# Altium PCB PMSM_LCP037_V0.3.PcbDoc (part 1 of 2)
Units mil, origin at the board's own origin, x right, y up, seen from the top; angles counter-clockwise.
Board outline 6102.36 x 5157.48 mil, 2 copper layers (Top Layer, Bottom Layer); 134 components, 72 nets, 340 pads, 815 vias.
Unrouted connection lines stored in the file: 2.
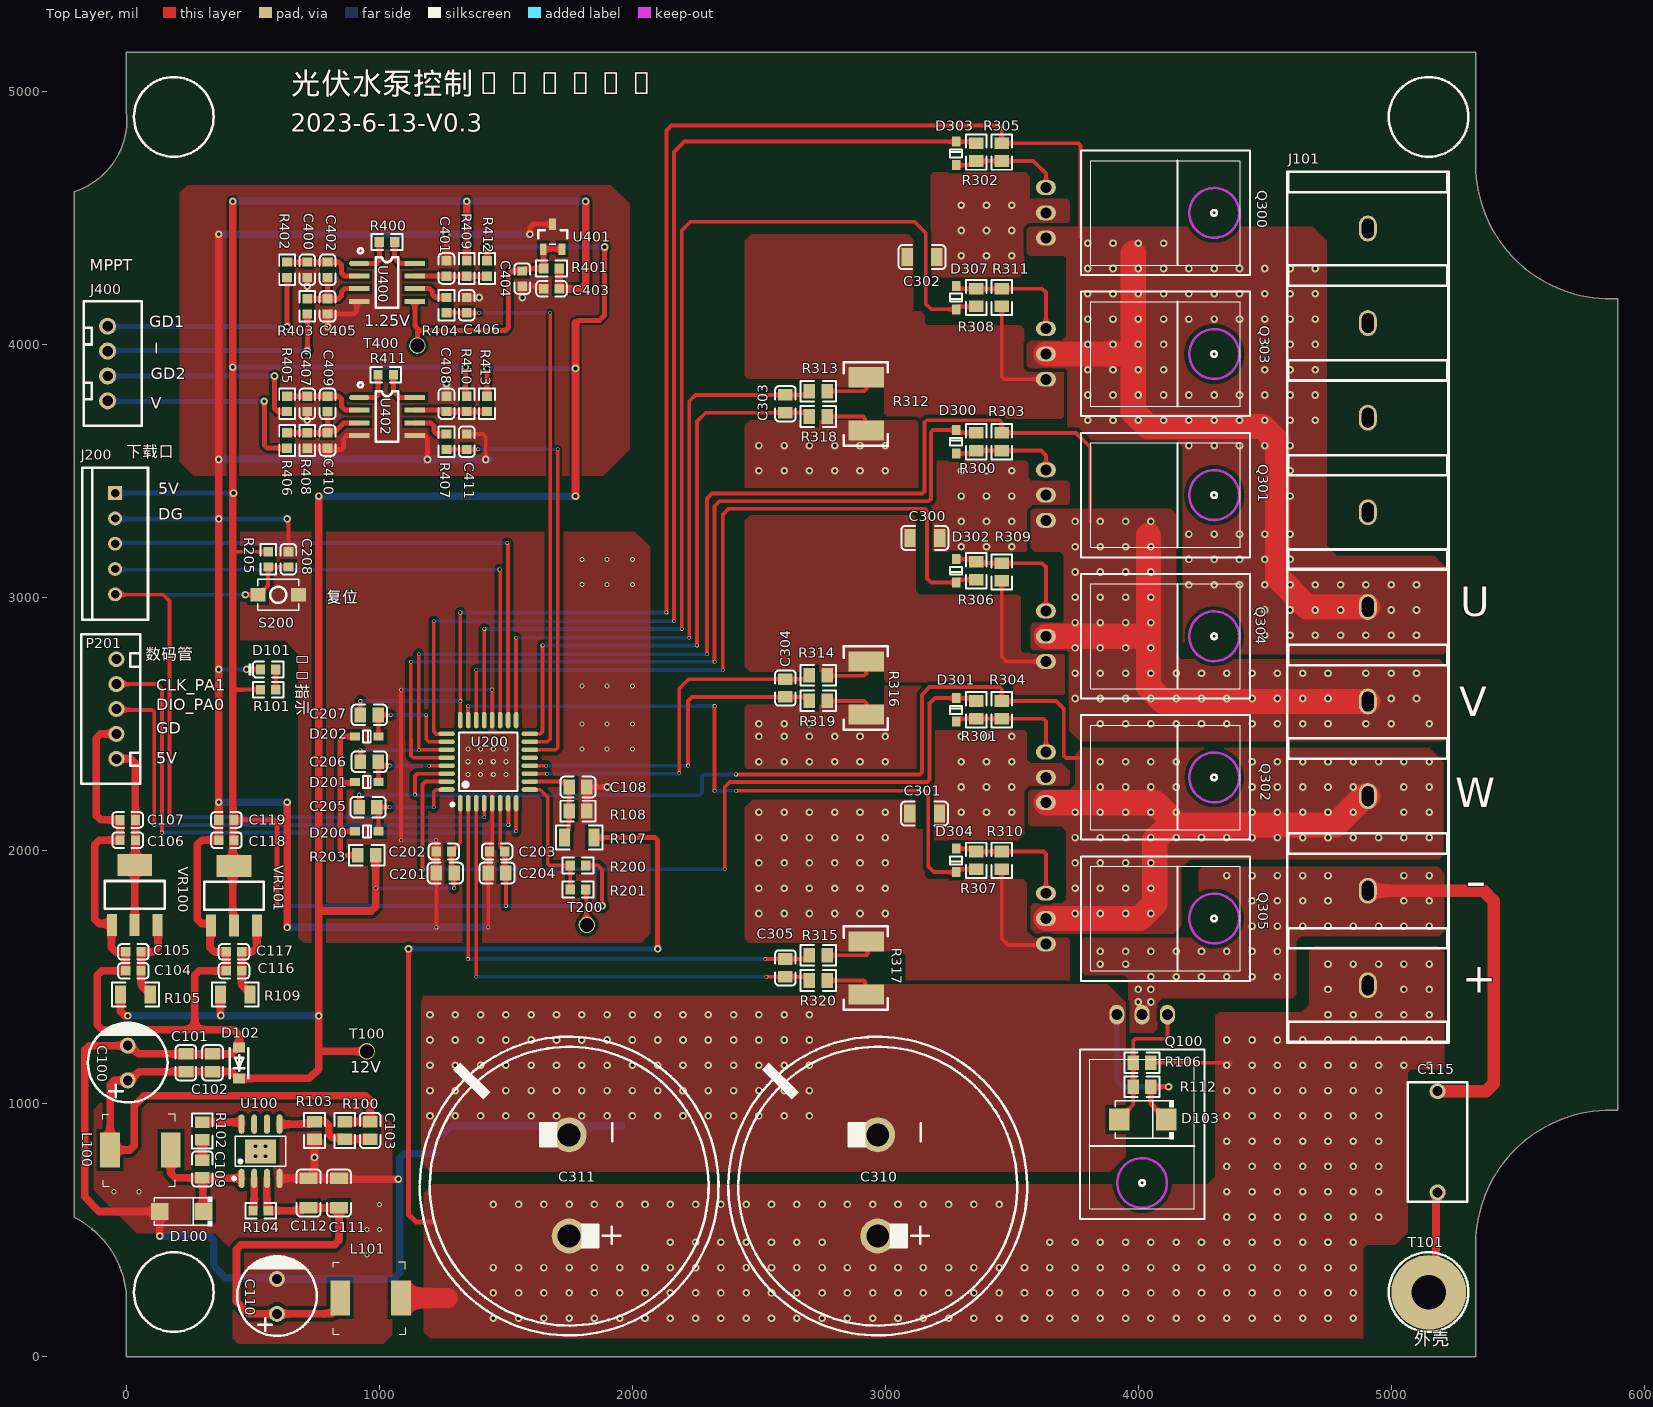
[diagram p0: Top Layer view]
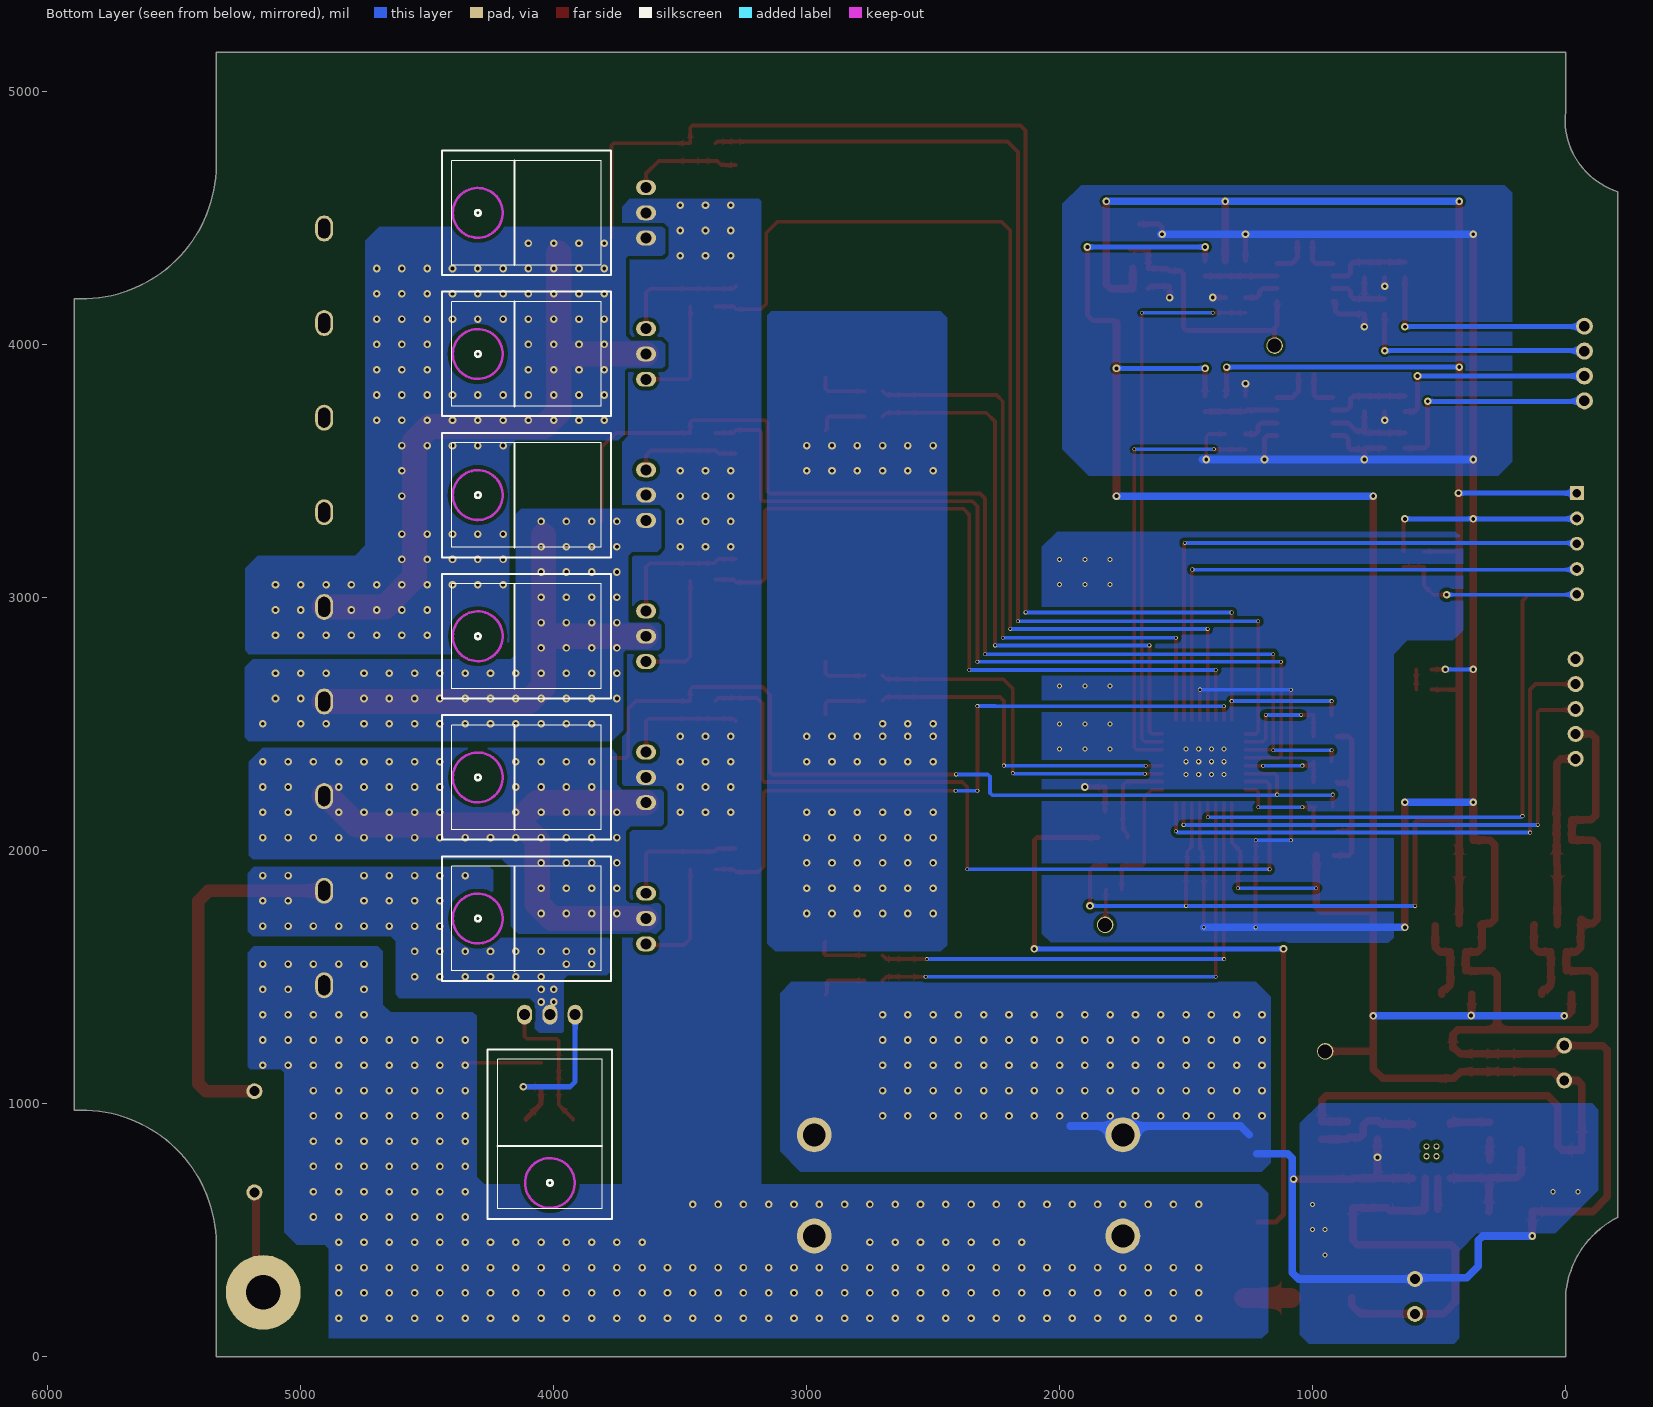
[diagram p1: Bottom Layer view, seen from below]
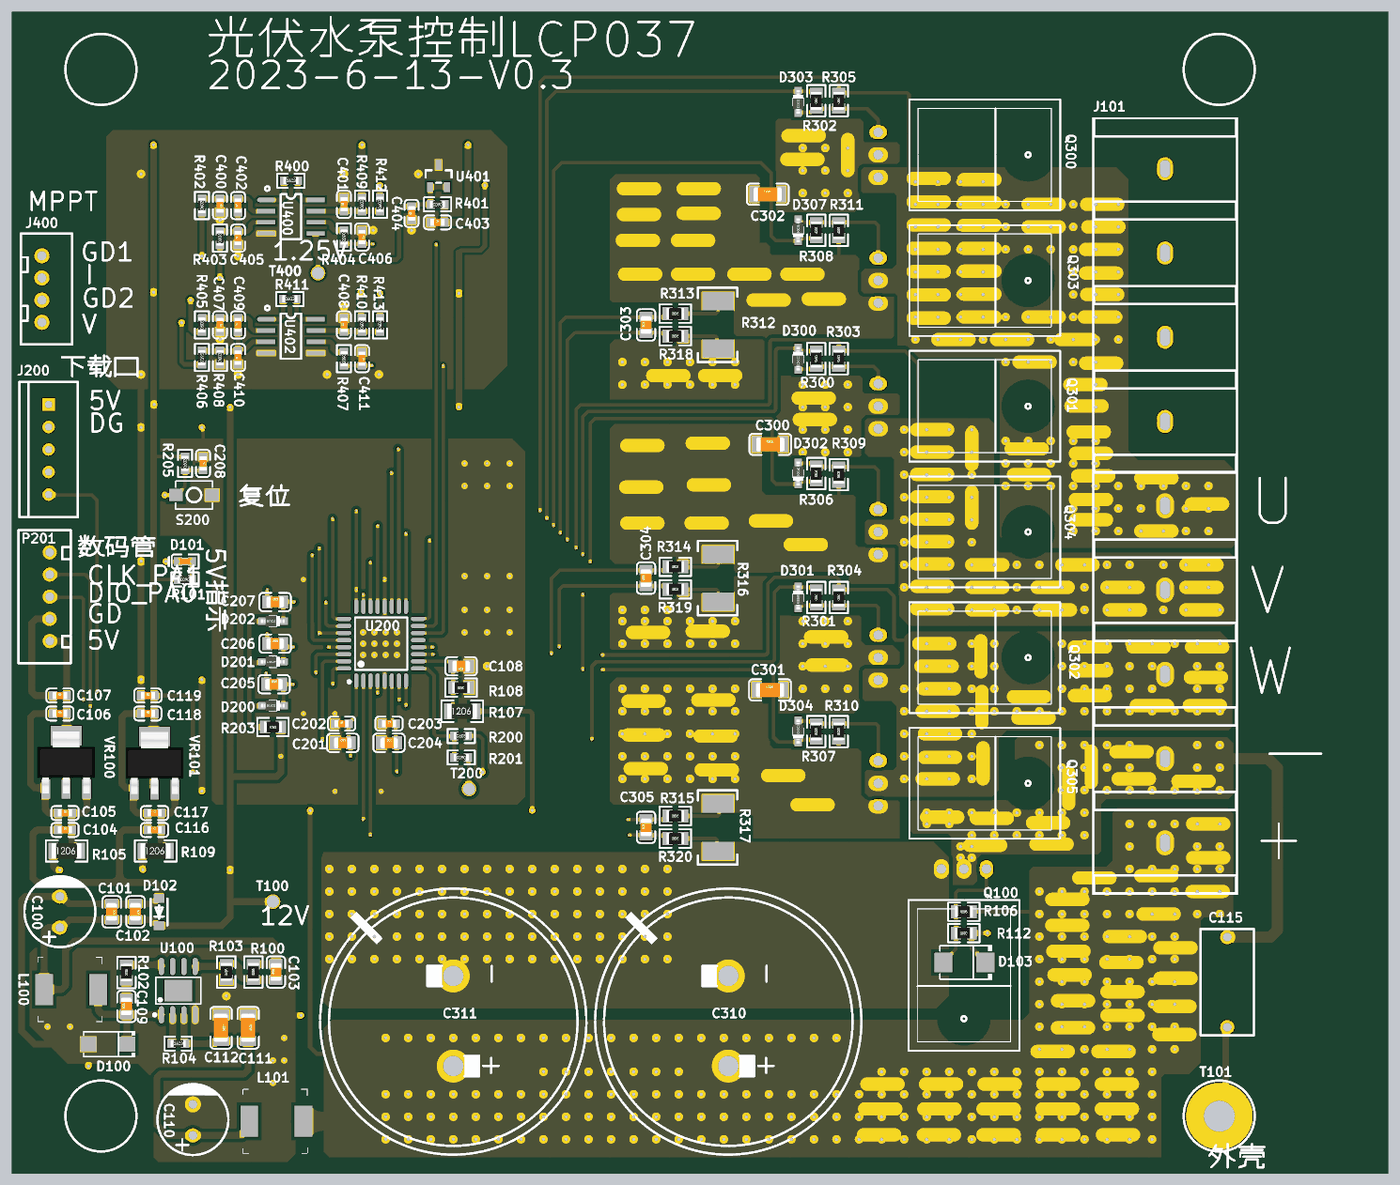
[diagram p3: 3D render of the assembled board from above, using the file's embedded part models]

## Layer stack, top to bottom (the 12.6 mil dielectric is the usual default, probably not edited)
Top Solder: solder mask 0.4, Solder Resist, Dk 3.5
Top Layer: signal copper 1.4
Dielectric 1: dielectric 12.6, FR-4, Dk 4.8
Bottom Layer: signal copper 1.4
Bottom Solder: solder mask 0.4, Solder Resist, Dk 3.5

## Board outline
0,-2.48 0,233.74 ccw(c-374.92,213) -206.69,548.7 -206.69,4603.82 ccw(c-297.17,4888.49) 0,4918.78 0,5155 5334.65,5155 5334.65,4682.56 ccw(c5866.14,4712.09) 5895.67,4180.59 5895.67,971.93 ccw(c5866.14,440.43) 5334.65,469.96 5334.65,-2.48

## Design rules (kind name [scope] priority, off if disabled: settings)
Clearance [All] p1: gap=10 ignorepadtopadclearanceinfootprint=FALSE
ComponentClearance [All] p1: gap=0 collisioncheckmode=3 verticalgap=0 showdistances=FALSE
HoleSize [All] p1: absolutevalues=TRUE maxlimit=500 minlimit=1 maxpercent=80.000 minpercent=20.000
HoleToHoleClearance [All] p1: gap=0 allowstackedmicrovias=TRUE
MinimumSolderMaskSliver [All] p1: minsoldermaskwidth=0
PlaneConnect [All] p1: planeconnectstyle=Direct reliefexpansion=20 reliefentries=4 reliefconductorwidth=10 reliefairgap=10
PolygonConnect [All] p1: connectstyle=Direct reliefconductorwidth=10 reliefentries=4 polygonreliefangle="90 Angle" airgapwidth=10
RoutingVias [All] p1: holewidth=10 width=15 viastyle="Through Hole" minholewidth=10 minwidth=15 maxholewidth=500 maxwidth=500
SilkToSilkClearance [All] p1: silktosilkclearance=0
SilkToSolderMaskClearance [IsPad] p1: minsilkscreentomaskgap=0 clearancetoexposedcopper=TRUE
SolderMaskExpansion [All] p1: expansion=4 istentingtop=FALSE
Width [All] p1: maxlimit=500 minlimit=6 preferedwidth=10
23 further rules are at their usual default settings.

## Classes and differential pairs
component class 04_AD623: C400 C401 C402 C403 C404 C405 C406 C407 C408 C409 C410 C411 J400 R400 R401 R402 R403 R404 R405 R406 R407 R408 R409 R410 R411 R412 R413 T400 U400 U401 U402
component class 03_Mos: C300 C301 C302 C303 C304 C305 C310 C311 D300 D301 D302 D303 D304 D307 Q300 Q301 Q302 Q303 Q304 Q305 R300 R301 R302 R303 R304 R305 R306 R307 R308 R309 R310 R311 R312 R313 R314 R315 R316 R317 R318 R319 R320
component class 02_MCU: C201 C202 C203 C204 C205 C206 C207 C208 D200 D201 D202 J200 P201 R200 R201 R203 R205 S200 T200 U200
component class 01_Power: C100 C101 C102 C103 C104 C105 C106 C107 C108 C109 C110 C111 C112 C115 C116 C117 C118 C119 D100 D101 D102 D103 J101 L100 L101 Q100 R100 R101 R102 R103 R104 R105 R106 R107 R108 R109 R112 T100 T101 U100 VR100 VR101

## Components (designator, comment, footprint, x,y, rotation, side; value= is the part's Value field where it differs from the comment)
C100 "470uF/25V" 47UF/100V 5,1090 r90 top
C101 "22uF (226) 20% 25V" 0805_C 235,1160 r270 top
C102 "100nF(104) 10% 50V" 0805_C 340,1160 r270 top
C103 "47pF (470) 5% 50V" 0805_C 963.31,892.52 r90 top
C104 "100nF (104) 10% 50V" 0603_C 27.48,1523.31 r0 top
C105 "10uF (106) 10% 10V" 0603_C 27.48,1598.31 r0 top
C106 "100nF (104) 10% 50V" 0603_C 5,2040 r0 top
C107 "10uF (106) 10% 10V" 0603_C 5,2120 r0 top
C108 "100nF(104) 10% 50V" 0805_C 1785,2250 r180 top
C109 "100nF(104) 10% 50V" 0805_C 300,740 r90 top
C110 "47uF/100V" 47UF/100V 595,167.2 r90 top
C111 "2.2uF (225) 10% 50V" 1206_C 840,645 r270 top
C112 "100nF (104) 10% 50V" 1206_C 720,645 r270 top
C115 "2.2nF (222) 10% 50V" "X1/Y1 500V" 5183.31,1047.52 r270 top
C116 "100nF (104) 10% 50V" 0603_C 425,1523.31 r0 top
C117 "10uF (106) 10% 10V" 0603_C 425,1598.31 r0 top
C118 "100nF (104) 10% 50V" 0603_C 395,2040 r0 top
C119 "10uF (106) 10% 10V" 0603_C 395,2120 r0 top
C201 "10uF (106) 10% 25V" 0805_C 1259.96,1910 r0 top
C202 "100nF (104) 10% 50V" 0603_C 1255,1995 r0 top
C203 "100nF (104) 10% 50V" 0603_C 1465,1995 r0 top
C204 "10uF (106) 10% 25V" 0805_C 1465,1910 r0 top
C205 "10uF (106) 10% 25V" 0805_C 955,2170 r0 top
C206 "10uF (106) 10% 25V" 0805_C 959.88,2350 r0 top
C207 "10uF (106) 10% 25V" 0805_C 959.88,2535 r0 top
C208 "100nF (104) 10% 50V" 0603_C 640,3150 r270 top
C300 "100nF (104) 10% 100V" 1206_C 3156.34,3235 r0 top
C301 "100nF (104) 10% 100V" 1206_C 3155,2145 r0 top
C302 "100nF (104) 10% 100V" 1206_C 3145,4345 r0 top
C303 "100pF (101) 5% 50V" 0805_C 2605,3765 r90 top
C304 "100pF (101) 5% 50V" 0805_C 2605,2641.22 r90 top
C305 "100pF (101) 5% 50V" 0805_C 2605,1535 r90 top
C310 "1000uF/250V" 1000UF/250V 2970,475 r90 top
C311 "1000uF/250V" 1000UF/250V 1750,475 r90 top
C400 "1nF (102) 10% 50V" 0603_C 715,4295 r270 top
C401 "100nF (104) 10% 50V" 0603_C 1265,4300 r90 top
C402 "47nF (473) 10% 50V" 0603_C 795,4295 r90 top
C403 "100nF (104) 10% 50V" 0603_C 1680.31,4220 r0 top
C404 "100nF (104) 10% 50V" 0603_C 1565,4260 r90 top
C405 "1nF (102) 10% 50V" 0603_C 795,4150 r90 top
C406 "100nF (104) 10% 50V" 0603_C 1345,4155 r270 top
C407 "1nF (102) 10% 50V" 0603_C 715,3765 r270 top
C408 "100nF (104) 10% 50V" 0603_C 1265,3765 r90 top
C409 "47nF (473) 10% 50V" 0603_C 795,3765 r90 top
C410 "1nF (102) 10% 50V" 0603_C 795,3620 r90 top
C411 "100nF (104) 10% 50V" 0603_C 1345,3615 r270 top
D100 "SS310" SS310 215,570 r180 top
D101 "绿灯 0603" 0603_LED_S1 560,2715 r0 top
D102 "SMF12A" "SMF12A - DUPLICATE" 445,1097.95 r90 top
D103 "SMBJ18A" SMBJ18A 4110,935 r180 top
D200 "1N4148WS T4" SOD-323 950,2075 r180 top
D201 "1N4148WS T4" SOD-323 949.88,2270 r180 top
D202 "1N4148WS T4" SOD-323 949.88,2450 r180 top
D300 "1N4148WS T4" SOD-323 3280,3615 r270 top
D301 "1N4148WS T4" SOD-323 3280,2555.04 r270 top
D302 "1N4148WS T4" SOD-323 3280,3105 r90 top
D303 "1N4148WS T4" SOD-323 3280,4755 r270 top
D304 "1N4148WS T4" SOD-323 3280,1960 r90 top
D307 "1N4148WS T4" SOD-323 3280,4185 r90 top
J101 "CON9" "CON9 9.5MM" 4907.48,1466.02 r90 top locked
J200 "SWD-KF2510-5P" 2.54_5P_PHI -45,3411.85 r270 top
J400 "CON4" XH2.54-4P -75,4071.85 r90 top
L100 "47uH/0650" 0650_47UH 45,815 r180 top
L101 "47uH/0650" 0650_47UH 955,230 r180 top
P201 "Header 5" XH2.54-5P -40,2755.28 r270 top
Q100 "NCEP1570" NCEP1570 4015,1507.48 r180 top locked
Q300 "NCEP1570" NCEP1570 3477.52,4520 r270 top locked
Q301 "NCEP1570" NCEP1570 3477.52,3404 r270 top
Q302 "NCEP1570" NCEP1570 3477.52,2288 r270 top
Q303 "NCEP1570" NCEP1570 3477.52,3962 r270 top
Q304 "NCEP1570" NCEP1570 3477.52,2846 r270 top
Q305 "NCEP1570" NCEP1570 3477.52,1730 r270 top
R100 "330KΩ (3303) ±1%" 0805_R 863.31,892.52 r90 top
R101 "10KΩ (1002) ±1%" 0603_R 560,2635 r180 top
R102 "22Ω (22R0) ±1%" 0805_R 300,890 r90 top
R103 "23.7KΩ" 0805_R 743.31,892.52 r90 top
R104 "30mΩ ±1%" 0603_R 530,575 r0 top
R105 "200Ω (2000) ±1%" 1206_R 35,1430 r0 top
R106 "20KΩ (2002) ±1%" 0805_R 4015,1160 r0 top
R107 "24KΩ (2402) ±1%" 1206_R 1790,2050 r0 top
R108 "1KΩ (1001) ±1%" 0805_R 1785,2155 r180 top
R109 "200Ω (2000) ±1%" 1206_R 430,1430 r0 top
R112 "10KΩ (1002) ±1%" 0805_R 4015,1065 r180 top
R200 "1KΩ (1001) ±1%" 0603_R 1785,1940 r0 top
R201 "1KΩ (1001) ±1%" 0603_R 1785,1845 r180 top
R203 "1KΩ (1001) ±1%" 0805_R 950,1980 r180 top
R205 "10KΩ (1002) ±1%" 0603_R 560,3150 r90 top
R300 "51Ω (51R0) ±1%" 0805_R 3360,3615 r270 top
R301 "51Ω (51R0) ±1%" 0805_R 3360,2555.04 r270 top
R302 "51Ω (51R0) ±1%" 0805_R 3360,4760 r270 top
R303 "100KΩ (1003) ±1%" 0805_R 3460,3615 r270 top
R304 "100KΩ (1003) ±1%" 0805_R 3460,2555.04 r270 top
R305 "100KΩ (1003) ±1%" 0805_R 3460,4760 r270 top
R306 "51Ω (51R0) ±1%" 0805_R 3360,3105 r90 top
R307 "51Ω (51R0) ±1%" 0805_R 3360,1960 r90 top
R308 "51Ω (51R0) ±1%" 0805_R 3360,4185 r90 top
R309 "100KΩ (1003) ±1%" 0805_R 3460,3100 r90 top
R310 "100KΩ (1003) ±1%" 0805_R 3460,1960 r90 top
R311 "100KΩ (1003) ±1%" 0805_R 3460,4185 r90 top
R312 "10mR 2512" R2512 2965,3790 r90 top
R313 "68Ω (68R0) ±1%" 0805_R 2735,3815 r0 top
R314 "68Ω (68R0) ±1%" 0805_R 2735,2691.22 r0 top
R315 "68Ω (68R0) ±1%" 0805_R 2735,1585 r0 top
R316 "10mR 2512" R2512 2965,2666.22 r90 top
R317 "10mR 2512" R2512 2965,1559.53 r90 top
R318 "68Ω (68R0) ±1%" 0805_R 2735,3715 r0 top
R319 "68Ω (68R0) ±1%" 0805_R 2735,2591.22 r0 top
R320 "68Ω (68R0) ±1%" 0805_R 2735,1485 r0 top
R400 "5.1KΩ (5101) ±1%" 0603_R 1030,4405 r0 top
R401 "220Ω (2200) ±1%" 0603_R 1680.32,4300 r180 top
R402 "1KΩ (1001) ±1%" 0603_R 635,4295 r90 top
R403 "1KΩ (1001) ±1%" 0603_R 715,4150 r90 top
R404 "100Ω (1000) ±1%" 0603_R 1265,4155 r270 top
R405 "1KΩ (1001) ±1%" 0603_R 635,3765 r90 top
R406 "20KΩ (2002) ±1%" 0603_R 635,3620 r270 top
R407 "100Ω (1000) ±1%" 0603_R 1265,3615 r270 top
R408 "1KΩ (1001) ±1%" 0603_R 715,3620 r90 top
R409 "0Ω (0R0) ±1%" 0603_R 1345,4300 r90 top
R410 "0Ω (0R0) ±1%" 0603_R 1345,3765 r90 top
R411 "0Ω (0R0) ±1%" 0603_R 1025,3880 r0 top
R412 "0Ω (0R0) ±1%" 0603_R 1425,4300 r90 top
R413 "0Ω (0R0) ±1%" 0603_R 1425,3765 r90 top
S200 "KEY" 按键3*4 519.76,3010 r0 top
T100 "Test" TESTPOINT 950,1205 r90 top
T101 "Test" 接地螺丝孔 5148.31,252.52 r0 top
T200 "Test" TESTPOINT 1820,1705 r90 top
T400 "Test" Testpoint 1150,3995 r90 top
U100 "TX4139" ESOP8 455,702.89 r0 top
U200 "LCP037BK32ET8" LQFP32 1330,2250 r270 top
U400 "AD623ARZ" SOIC8 925,4320 r0 top
U401 "ME432" ME432 1647.6,4376.6 r270 top
U402 "AD623ARZ" SOIC8 925,3790 r0 top
VR100 "AMS1117-5.0" SOT-223 32.48,1823.31 r270 top
VR101 "AMS1117-5.0" SOT-223 425,1820 r270 top

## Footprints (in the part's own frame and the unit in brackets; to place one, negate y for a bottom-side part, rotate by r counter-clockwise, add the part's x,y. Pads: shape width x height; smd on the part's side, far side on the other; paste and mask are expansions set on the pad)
2.54_5P_PHI [mil]
  rect 55x55 hole 33: 1(0,0)
  round 55 hole 33: 2(100,0) 3(200,0) 4(300,0) 5(400,0)
  silkscreen extent -100,-130 500,130
47UF/100V [mm] "8*14"
  round 1.6 hole 1: 1(0,0) 2(3.5,0)
  silkscreen extent -2.21,-4 5.79,4
0603_C [mm]
  rect 0.93x0.98 smd: 1(-0.77,0) 2(0.77,0)
  silkscreen extent -1.53,-0.79 1.54,0.79, body extent -0.8,-0.4 0.8,0.4, height 0.3
0603_LED_S1 [mm]
  rect 0.93x0.98 smd: A(0.77,0) K(-0.77,0)
  silkscreen extent -1.97,-0.79 1.54,0.79, body extent -0.8,-0.4 0.8,0.4, height 0.6
0603_R [mm]
  rect 0.93x0.98 smd: 1(-0.77,0) 2(0.77,0)
  silkscreen extent -1.53,-0.79 1.54,0.79, body extent -0.85,-0.4 0.85,0.4, height 0.56
0650_47UH [mm]
  rect 2x3.5 smd: 1(-3.302,0) 2(2.794,0)
  silkscreen extent -3.76,-3.62 3.52,3.62
0805_C [mm]
  rect 1.16x1.47 smd: 1(-0.89,0) 2(0.89,0)
  silkscreen extent -1.77,-1.04 1.77,1.04, body extent -1,-0.62 1,0.63, height 0.77
0805_R [mm]
  rect 1.16x1.47 smd: 1(-0.89,0) 2(0.89,0)
  silkscreen extent -1.77,-1.04 1.77,1.03, body extent -1,-0.62 1,0.63, height 0.49
1000UF/250V [mm]
  round 3.5 hole 2.3: 1(0,0) 2(10.16,0)
  silkscreen extent -9.99,-15 20.01,15
1206_C [mm]
  rect 1.13x1.8 smd: 1(-1.49,0) 2(1.49,0)
  silkscreen extent -2.36,-1.2 2.35,1.2, body extent -1.6,-0.81 1.6,0.79, height 1
1206_R [mm]
  rect 1.13x1.8 smd: 1(-1.49,0) 2(1.49,0)
  silkscreen extent -2.36,-1.2 2.35,1.2, body extent -1.7,-0.86 1.65,0.87, height 0.85
"CON9 9.5MM" [mm]
  oval 2.6x1.8 hole 1.2 slot 2 at 0 deg: 1(0,0) 2(9.5,0) 3(19,0) 4(28.5,0) 5(38,0) 6(47.5,0) 7(57,0) 8(66.5,0) 9(76,0)
  silkscreen extent -5.75,-8.1 81.69,8.1
ESOP8 [mm]
  oval 0.602x1.941 smd: 1(0,0) 2(1.27,0) 3(2.54,0) 4(3.81,0) 5(3.81,5.441) 6(2.54,5.441) 7(1.27,5.441) 8(0,5.441)
  rect 3.098x2.41 smd: 9(1.905,2.72)
  silkscreen extent -0.9,-0.15 4.43,4.24
LQFP32 [mm]
  oval 1.65x0.48 smd: 1(1.635,-0.26) 2(1.635,0.54) 3(1.635,1.34) 4(1.635,2.14) 5(1.635,2.94) 6(1.635,3.74) 7(1.635,4.54) 8(1.635,5.34) 17(-6.715,5.34) 18(-6.715,4.54) 19(-6.715,3.74) 20(-6.715,2.94) 21(-6.715,2.14) 22(-6.715,1.34) 23(-6.715,0.54) 24(-6.715,-0.26)
  oval 0.48x1.65 smd: 9(0.26,6.715) 10(-0.54,6.715) 11(-1.34,6.715) 12(-2.14,6.715) 13(-2.94,6.715) 14(-3.74,6.715) 15(-4.54,6.715) 16(-5.34,6.715) 25(-5.34,-1.635) 26(-4.54,-1.635) 27(-3.74,-1.635) 28(-2.94,-1.635) 29(-2.14,-1.635) 30(-1.34,-1.635) 31(-0.54,-1.635) 32(0.26,-1.635)
  silkscreen extent -5.49,-1.21 1.91,5.49
ME432 [mm]
  rect 1.15x0.7 smd: 1(0,0) 2(-2.499,0.95) 3(0,1.9)
  silkscreen extent -1.9,-0.51 -0.49,2.41
NCEP1570 [mm]
  oval 1.5x2 hole 1.1: 1(-2.54,4) 2(0,4) 3(2.54,4)
  Keep-Out Layer circle w0.254: c0,20.9 r2.5
  silkscreen extent -6.25,7.5 6.25,24.5
R2512 [mil]
  rect 80x140 smd: 1(-130,40) 2(80,40)
  silkscreen extent -190,-45 140,130
SMBJ18A [mil] "DO-214AA"
  rect 80.61x86.31 smd: 1(0,0) 2(185.89,0)
  silkscreen extent -30,-77 201,77
"SMF12A - DUPLICATE" [mm] "SOD123F"
  rect 1x1.2 smd: 1(0,0) 2(3.1,0)
  silkscreen extent 0.03,-0.93 3.04,0.95
SOD-323 [mm]
  rect 1x0.83 smd: 1(1.18,0) 2(-1.18,0)
  silkscreen extent -0.4,-0.6 0.4,0.6, body extent -1.35,-0.62 1.35,0.63, height 1.1
SOIC8 [mil]
  oval 80x20 smd: 1(-5,0)
  rect 80x20 smd: 2(-5,-50) 3(-5,-100) 4(-5,-150) 5(215,-150) 6(215,-100) 7(215,-50) 8(215,0)
  silkscreen extent -10,-175 150,60
SOT-223 [mm]
  rect 2.2x1 smd: 1(3,-2.3) 2(3,0) 3(3,2.3)
  rect 2.2x3.5 smd: 2(-3,0)
  silkscreen extent -1.4,-3 1.4,3, body extent -3.49,-3.24 3.49,3.24, height 1.64
SS310 [mm]
  rect 1.8x1.7 smd paste+0 mask+0.051: 1(-2.26,-0.047) 2(2.125,-0.047)
  silkscreen extent -3.17,-1.52 2.66,1.43
TESTPOINT [mil]
  round 65 hole 55: 1(0,0)
Testpoint [mil]
  round 65 hole 55: 1(0,0)
"X1/Y1 500V" [mm]
  round 1.6 hole 1: 1(0,0) 2(10.16,0)
  silkscreen extent -0.92,-3 11.08,3
XH2.54-4P [mm]
  round 1.7 hole 1.05: 1(0,0) 2(-2.5,0) 3(-5,0) 4(-7.5,0)
  silkscreen extent -10,-3.42 2.5,2.37
XH2.54-5P [mm]
  round 1.6 hole 1 paste+0 mask+0.05: 1(0,0) 2(2.5,0) 3(5,0) 4(7.5,0) 5(10,0)
  silkscreen extent -2.5,-3.53 12.5,2.38
按键3*4 [mm]
  rect 1.53x1.36 smd: 1(0,0) 2(4.07,0)
  silkscreen extent -0.04,-1.58 4.11,1.58
接地螺丝孔 [mm]
  round 7.5 hole 3.5: 6(0,0)

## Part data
C100 C110: library part CapSMT220u_16V
C101: library part "0805 22uF (226) 20% 25V", "贴片电容", Package=0805, SuppliersPartNumber=C45783
C102 C108 C109: library part "0805 100nF(104) 10% 50V", "贴片电容", Package=0805, SuppliersPartNumber=C49678
C103: library part "0805 47pF (470) 5% 50V", "贴片电容", Package=0805, SuppliersPartNumber=C14857
C104 C106 C116 C118 C202 C203 C208 C401 C403 C404 C406 C408 C411: library part "0603 100nF (104) 10% 50V", "贴片电容", Package=0603, SuppliersPartNumber=C14663
C105 C107 C117 C119: library part "0603 10uF (106) 10% 10V", "贴片电容", Package=0603, SuppliersPartNumber=C19702
C111: library part "1206 2.2uF (225) 10% 50V", "贴片电容", Package=1206, SuppliersPartNumber=C12656
C112 C300 C301 C302: library part "1206 100nF (104) 10% 50V", "贴片电容", Package=1206, SuppliersPartNumber=C24497
C115: library part "0603 2.2nF (222) 10% 50V", "贴片电容", Package=0603, SuppliersPartNumber=C1604
C201 C204 C205 C206 C207: library part "0805 10uF (106) 10% 25V", "贴片电容", Package=0805, SuppliersPartNumber=C15850
C303 C304 C305: library part "0805 100pF (101) 5% 50V", "贴片电容", Package=0805, SuppliersPartNumber=C1790
C310 C311: library part CAP2, "电解电容"
C400 C405 C407 C410: library part "0603 1nF (102) 10% 50V", "贴片电容", Package=0603, SuppliersPartNumber=C1588
C402 C409: library part "0603 47nF (473) 10% 50V", "贴片电容", Package=0603, SuppliersPartNumber=C1622
D101: library part "0603 绿灯", "发光二极管", Package=0603, SuppliersPartNumber=C72043
D103: library part 1N4746A
D200 D201 D202 D300 D301 D302 D303 D304 D307: library part "SOD-323 1N4148WS T4", "二极管", Package=SOD-323, SuppliersPartNumber=C2128
J200: library part ST-LINK-SWD
L100 L101: library part Inductor
P201: "Header, 5-Pin"
Q100 Q300 Q301 Q302 Q303 Q304 Q305: library part IRFB4127PBF
R100: library part "0805 330KΩ (3303) 1%", "贴片电阻", Package=0805, SuppliersPartNumber=C17629
R101 R205: library part "0603 10KΩ (1002) 1%", "贴片电阻", Package=0603, SuppliersPartNumber=C25804
R102 R103: library part "0805 22Ω (22R0) 1%", "贴片电阻", Package=0805, SuppliersPartNumber=C17561
R104: library part "0603 100KΩ (1003) 1%", "贴片电阻", Package=0603, SuppliersPartNumber=C25803
R105 R109: library part "1206 300Ω (3000) 1%", "贴片电阻", Package=1206, SuppliersPartNumber=C17887
R106: library part "0805 20KΩ (2002) 1%", "贴片电阻", Package=0805, SuppliersPartNumber=C4328
R107: library part "1206 0Ω (0R0) 1%", "贴片电阻", Package=1206, SuppliersPartNumber=C17888
R108 R203: library part "0805 1KΩ (1001) 1%", "贴片电阻", Package=0805, SuppliersPartNumber=C17513
R112: library part "0805 10KΩ (1002) 1%", "贴片电阻", Package=0805, SuppliersPartNumber=C17414
R200 R201 R402 R403 R405 R408: library part "0603 1KΩ (1001) 1%", "贴片电阻", Package=0603, SuppliersPartNumber=C21190
R300 R301 R302 R306 R307 R308: library part "0805 51Ω (51R0) 1%", "贴片电阻", Package=0805, SuppliersPartNumber=C17738
R303 R304 R305 R309 R310 R311: library part "0805 100KΩ (1003) 1%", "贴片电阻", Package=0805, SuppliersPartNumber=C17407
R312 R316 R317: library part Res10K
R313 R314 R315 R318 R319 R320: library part "0805 68Ω (68R0) 1%", "贴片电阻", Package=0805, SuppliersPartNumber=C17802
R400: library part "0603 5.1KΩ (5101) 1%", "贴片电阻", Package=0603, SuppliersPartNumber=C23186
R401: library part "0603 220Ω (2200) 1%", "贴片电阻", Package=0603, SuppliersPartNumber=C22962
R404 R407: library part "0603 100Ω (1000) 1%", "贴片电阻", Package=0603, SuppliersPartNumber=C22775
R406: library part "0603 20KΩ (2002) 1%", "贴片电阻", Package=0603, SuppliersPartNumber=C4184
R409 R410 R411 R412 R413: library part "0603 0Ω (0R0) 1%", "贴片电阻", Package=0603, SuppliersPartNumber=C21189
T100 T101 T200 T400: library part TestPad
U200: library part LCP037BT32EU8
U400 U402: library part AD623
U401: library part "CJ431 0.5%431", "电压基准", Package=SOT-23, SuppliersPartNumber=C3113
VR100 VR101: library part "SOT-223 AMS1117-5.0", "低压差线性稳压(LDO)", Package=SOT-223, SuppliersPartNumber=C6187

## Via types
v1: diameter 30, hole 15, Top Layer to Bottom Layer, 713 vias
v2: diameter 15, hole 10, Top Layer to Bottom Layer, 65 vias
v3: diameter 20, hole 12, Top Layer to Bottom Layer, 33 vias
v4: diameter 24, hole 15, Top Layer to Bottom Layer, 4 vias

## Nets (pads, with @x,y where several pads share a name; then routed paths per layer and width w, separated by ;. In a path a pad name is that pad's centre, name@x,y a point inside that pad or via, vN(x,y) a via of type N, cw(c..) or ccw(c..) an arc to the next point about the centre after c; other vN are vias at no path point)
5V: C106.2 C107.2 P201.5 VR100.2 | length 722.6
  Top Layer w30: P201.5@-40,2361.57 17.74,2361.57 35.32,2344 C107.2@35.32,2120 C106.2@35.32,2040 35.32,1944.25 VR100.2@32.48,1941.42 VR100.2@32.48,1705.2
5VDD: C118.2 C119.2 C203.2 C204.2 C403.2 J200.1 R101.2 R200.2 R205.2 R401.1 R409.2 R410.2 U200.6 VR101.2 | length 9177.4
  Top Layer w15: 420.32,2635 R101.2@529.68,2635 ; 420.32,3180 420.63,3180.32 R205.2@560,3180.32 ; U200.6@1477.24,2185.63 1477.24,2014.06 1495.31,1995.98 C203.2@1495.31,1995 1495.31,1914.72 C204.2@1500.04,1910 v2(1500.04,1780.04) v2(1500.04,1780.04) ; R200.2@1815.32,1940 1865,1940 1869.99,1935.01 1880,1925 v1(1880,1780)
  Top Layer w20: C119.2@425.32,2120 583.28,2120 595,2108.28 v2(595,1780) ; v1(1340,3910) 1340,3800.32 R410.2@1345,3795.32
  Top Layer w30: VR101.2@420,1710 420,1946.22 420.32,1946.54 420.32,2635 420.32,3180 420.32,4564.68 v1(420,4565) ; R409.2@1345,4330.32 v1(1345,4565) ; R401.1@1710.63,4300 C403.2@1710.63,4220 1797.43,4220 1815,4237.57 v1(1815,4565)
  Bottom Layer w15: v2(595,1780) v2(595,1780) v2(1500.04,1780.04) 1876.67,1780.04 v1@1877.52,1779.2
  Bottom Layer w20: J200.1@-45,3411.85 v1(423.15,3411.85) v1@425,3410 ; v1(420,3910) v1(1340,3910)
  Bottom Layer w30: v1(420,4565) v1(1345,4565) v1(1815,4565)
12VDD: C100.1 C101.2 C102.2 C103.2 C201.2 C202.2 D102.1 L100.2 R100.2 R105.1 R109.1 R203.1 R412.2 R413.2 T100.1 U200.1 | length 10097.3
  Top Layer w15: v2(1295,1850) C201.2@1295,1910 1285.31,1919.69 C202.2@1285.31,1995 1285.31,1995.98 1319.76,2030.43 U200.1@1319.76,2185.63
  Top Layer w20: R413.2@1425,3795.32 v1(1425,3905) ; R412.2@1425,4330.32 v1(1425,4385) ; 1775,4085 1785,4095 1870,4095 1890,4115 v1(1890,4385)
  Top Layer w30: R105.1@-23.66,1430 -23.66,1362.57 v1@-6.09,1345 ; v1@371.34,1348.66 R109.1@371.34,1430 ; v1(760,3400) 760,1755 ; R100.2@863.31,927.56 C103.2@963.31,927.56 963.31,1011.69 945,1030 70,1030 30,990 30,832.57 12.43,815 L100.2@-65,815 -65,1072.43 -47.43,1090 C100.1@5,1090 13.93,1090 48.89,1124.96 C101.2@235,1124.96 C102.2@340,1124.96 414.06,1124.96 441.06,1097.95 D102.1@445,1097.95 722.95,1097.95 760,1135 760,1215 ; T100.1@950,1205 770,1205 760,1215 ; R203.1@985.04,1980 985.04,1777.57 967.47,1760 765,1760 760,1755 ; v1(1775,3400) v1(1775,3905) 1775,4085 ; 760,1215 v1(760,1345) 760,1755
  Bottom Layer w15: v2(985,1850) v2(1295,1850)
  Bottom Layer w20: v1(1425,3905) v1(1775,3905) ; v1(1425,4385) v1(1890,4385)
  Bottom Layer w30: v1(5,1345) v1(760,1345) ; v1(760,3400) v1(1775,3400)
  other v1: 373.17,1346.83
ADC1-V: C411.2 R407.2 U200.14 | length 1733.4
  Top Layer w15: R407.2@1265,3584.68 C411.2@1345,3584.68 1389.69,3584.68 v2(1390,3585) ; U200.14@1594.37,2397.24 1696.21,2397.24 1705,2406.03 v2(1705,3585)
  Bottom Layer w15: v2(1390,3585) v2(1705,3585)
ADC2-I: C406.2 R404.2 U200.15 | length 2180.1
  Top Layer w15: R404.2@1265,4124.68 C406.2@1345,4124.68 v2(1394.69,4124.68) ; U200.15@1594.37,2428.74 1663.74,2428.74 1675,2440 v2@1675,4124.68
  Bottom Layer w15: v2(1394.69,4124.68) 1674.69,4124.68 v2(1675,4125)
DGND: C100.2 C101.1 C102.1 C104.1 C105.1 C106.1 C107.1 C108.1 C110.2 C111.1 C112.1 C116.1 C117.1 C118.1 C119.1 C201.1 C202.1 C203.1 C204.1 C208.1 C310.2 C311.2 C400.2 C401.2 C403.1 C404.1 C405.1 C406.1 C407.2 C408.2 C410.1 C411.1 D100.2 D101.K D102.2 D103.1 J200.2 P201.4 Q100.3 R103.1 R108.1 R112.1 R317.1 R320.2 R408.1 S200.2 U100.4 U200.5 U200.20 U400.4 U401.2 U402.4 U402.5 VR100.1 VR101.1 | length 19694.7
  Top Layer w15: v1(475,2715) D101.K@529.69,2715 ; C208.1@640,3180.31 640,3285 640,3303.65 v1@635.96,3307.69 ; v2@1085,2635 v2(1085.31,2634.69) v2(1085.31,2039.69) ; v2(1225,1695) 1225,1909.92 C201.1@1224.92,1910 1224.69,1910.24 C202.1@1224.69,1995 v2(1224.69,2039.69) v2@1225,2040 ; C408.2@1265,3795.32 v1(1265,3845) ; C411.1@1345,3645.32 1409.69,3645.32 1420,3635 v1(1420,3545) ; v2(1429.96,1695.04) v2(1429.96,1695.04) C204.1@1429.96,1910 1434.69,1914.72 C203.1@1434.69,1995 1445,2005.31 1445,2035 1445.75,2035.75 U200.5@1445.75,2185.63 ; v2(1445,2635) 1445.75,2634.25 U200.20@1445.75,2514.37 ; R320.2@2770.04,1485 2915,1485 2920,1480 2920,1434.53 R317.1@2925,1429.53 ; v1@635.96,3307.69 635,3308.65 v1(635,3310) 635.96,3309.04 v1@635.96,3307.69
  Top Layer w20: R408.1@715,3589.69 C410.1@795,3589.68 ; v1(715,3700) C407.2@715,3734.68 ; v1(715,4230) C400.2@715,4264.68 ; v1(795,3545) C410.1@795,3589.68 ; v1(795,4070) C405.1@795,4119.68 898.28,4119.68 910,4131.4 910,4170 U400.4@920,4170 ; U402.4@920,3640 872.18,3640 858.59,3626.41 858.59,3593.79 849.8,3585 799.68,3585 C410.1@795,3589.68 ; U402.5@1140,3640 1178.28,3640 1190,3628.28 v1(1190,3545) ; C401.2@1265,4330.32 v1(1265,4435) ; C406.1@1345,4185.32 v1(1394.69,4185.32) v1@1395,4185 ; v1(1565,4185) C404.1@1565,4229.68 1641.3,4229.68 1650,4220.98 C403.1@1650,4220 ; v1(1595,4435) 1595,4463.28 1606.72,4475 U401.2@1685,4475 ; R108.1@1820.04,2155 C108.1@1820.04,2250 v1(1900,2250) ; D103.1@4110,935 4110,937.85 4050.04,997.81 R112.1@4050.04,1065 v1(4120,1065)
  Top Layer w30: VR100.1@-62.76,1727.57 VR100.1@-60,1724.82 ; VR100.1@-58.07,1705.2 VR100.1@-60,1707.13 ; P201.4@-40,2460 -102.43,2460 -120,2442.43 -120,2137.57 -102.43,2120 C107.1@-25.32,2120 C106.1@-25.32,2040 -107.43,2040 -125,2022.43 -125,1727.57 -107.43,1710 -62.76,1710 -62.76,1709.88 VR100.1@-60,1707.13 ; v1(131.56,475) 131.35,475.2 D100.2@131.35,571.83 -106.83,571.83 -165,630 -165,1210.23 -147.43,1227.8 C100.2@5,1227.8 13.93,1227.8 46.69,1195.04 C101.1@235,1195.04 C102.1@340,1195.04 416.1,1195.04 441.06,1220 D102.2@445,1220 445,1270 425,1290 270,1290 ; v1(365,4435) 364.68,4434.68 C119.1@364.68,2120 C118.1@364.68,2040 297.57,2040 280,2022.43 280,1727.57 297.57,1710 329.76,1710 334.45,1705.31 VR101.1@334.45,1701.89 330,1697.44 330,1615.88 347.57,1598.31 C117.1@394.68,1598.31 C116.1@394.68,1523.31 287.57,1523.31 270,1505.73 270,1290 ; U100.4@605,702.89 605.38,703.28 839.62,703.28 C111.1@840,703.66 843.66,700 v1(1075,700) ; v1(635,1695) v1(635,2190) ; C112.1@720,703.66 733.19,703.66 743.31,713.78 v1(743.31,785.63) R103.1@743.31,857.48 ; VR100.1@-60,1707.13 -60,1615.88 -42.43,1598.31 C105.1@-2.83,1598.31 C104.1@-2.83,1523.31 -97.43,1523.31 -115,1505.73 -115,1310 -95,1290 270,1290
  Bottom Layer w15: v1(365,2715) v1(475,2715) ; v2@1085,2040 v2(1085.31,2039.69) v2(1224.69,2039.69) ; v2(1085.31,2634.69) 1444.69,2634.69 v2(1445,2635)
  Bottom Layer w20: J200.2@-45,3311.85 -43.15,3310 v1(365,3310) v1(635,3310) ; Q100.3@3915,1350 3915,1085 3935,1065 v1(4120,1065)
  Bottom Layer w30: v1(131.56,475) 327.43,475 345,457.43 345,355 390,310 590,310 C110.2@595,305 1055,305 1080,330 1080,695 v1(1075,700) 1080,705 1080,782.43 1097.57,800 1220,800 ; v1(365,2190) v1(635,2190) ; v1(365,3545) v1(795,3545) v1(1190,3545) v1(1420,3545) 1435,3545 ; v1(365,4435) v1(1265,4435) v1(1595,4435) v1@1600,4435 ; v1(635,1695) v2(1225,1695) v2(1429.96,1695.04) ; 1250,875 1285,910 1957.99,910 1958.66,909.33
  other v1: 1200,950 1300,950 1400,950 1500,950 1600,950 1700,950 1800,950 1900,950 2000,950 2100,950 2200,950 2300,950 2400,950 2500,950 2600,950 2700,950 1200,1050 1300,1050 1400,1050 1500,1050 1600,1050 1700,1050 1800,1050 1900,1050 2000,1050 2100,1050 2200,1050 2300,1050 2400,1050 2500,1050 2600,1050 2700,1050 1200,1150 1300,1150 1400,1150 1500,1150 1600,1150 1700,1150 1800,1150 1900,1150 2000,1150 2100,1150 2200,1150 2300,1150 2400,1150 2500,1150 2600,1150 2700,1150 1200,1250 1300,1250 1400,1250 1500,1250 1600,1250 1700,1250 1800,1250 1900,1250 2000,1250 2100,1250 2200,1250 2300,1250 2400,1250 2500,1250 2600,1250 2700,1250 1200,1350 1300,1350 1400,1350 1500,1350 1600,1350 1700,1350 1800,1350 1900,1350 2000,1350 2100,1350 2200,1350 2300,1350 2400,1350 2500,1350 2600,1350 2700,1350
  other v3: 950,400 950,500 1000,500 1000,600 -50,650 50,650 1350,2300 1400,2300 1450,2300 1500,2300 1350,2350 1400,2350 1450,2350 1500,2350 1350,2400 1400,2400 1450,2400 1500,2400 1800,2400 1900,2400 2000,2400 1800,2500 1900,2500 2000,2500 1800,2650 1900,2650 2000,2650 1800,3050 1900,3050 2000,3050 1800,3150 1900,3150 2000,3150
GND: C115.1 J101.2 Q100.2 | length 1471.1
  Top Layer w50: J101.2@4907.48,1840.04 5364.96,1840.04 5405,1800 5405,1076.81 5375.71,1047.52 C115.1@5183.31,1047.52
  other v1: 4000,1400 4050,1400 4000,1450 4050,1450 4050,1500 4150,1500 4250,1500 4350,1500 4450,1500 4550,1500 3850,1550 3950,1550 3850,1600 3950,1600 4050,1600 4150,1600 4250,1600 4350,1600 4450,1600 4550,1600 4450,1700 4550,1700 4650,1700 4750,1700 4850,1700 4950,1700 5050,1700 5150,1700 4450,1800 4550,1800 4650,1800 4750,1800 5050,1800 5150,1800 4350,1900 4450,1900 4550,1900 4650,1900 4750,1900 5050,1900 5150,1900
ISENCE: C301.1 Q305.3 R310.1 R312.1 R315.2 R316.1 R317.2 R318.2 R319.2 | length 1082
  Top Layer w15: R315.2@2770.04,1585 2924.99,1585 2930,1590.01 2930,1634.53 R317.2@2925,1639.53 ; R319.2@2770.04,2591.22 2771.26,2590 2916.21,2590 2925,2581.21 R316.1@2925,2536.22 ; R318.2@2770.04,3715 2911.21,3715 2920,3706.21 2920,3665 R312.1@2925,3660 ; R310.1@3460,1924.96 3460,1650 3485,1625 3630,1625 Q305.3@3635,1630
  other v1: 2500,1750 2600,1750 2700,1750 2800,1750 2900,1750 3000,1750 2500,1850 2600,1850 2700,1850 2800,1850 2900,1850 3000,1850 2500,1950 2600,1950 2700,1950 2800,1950 2900,1950 3000,1950 2500,2050 2600,2050 2700,2050 2800,2050 2900,2050 3000,2050 2500,2150 2600,2150 2700,2150 2800,2150 2900,2150 3000,2150 2500,2350 2600,2350 2700,2350 2800,2350 2900,2350 3000,2350 2500,2450 2600,2450 2700,2450 2800,2450 2900,2450 3000,2450 2500,2500 2600,2500 2700,2500 2500,3500 2600,3500 2700,3500 2800,3500 2900,3500 3000,3500 2500,3600 2600,3600 2700,3600 2800,3600 2900,3600 3000,3600
IU: C302.1 Q303.3 R311.1 R312.2 R313.2 | length 662.6
  Top Layer w15: R313.2@2770.04,3815 2916.21,3815 2925,3823.79 R312.2@2925,3870 ; R311.1@3460,4149.96 3460,3870.79 3468.79,3862 Q303.3@3635,3862
IV: C300.1 Q304.3 R309.1 R314.2 R316.2 | length 689.4
  Top Layer w15: R314.2@2770.04,2691.22 2771.26,2690 2916.21,2690 2925,2698.79 R316.2@2925,2746.22 ; R309.1@3460,3064.96 3460,2765 3479,2746 Q304.3@3635,2746
M-NRST: C208.2 J200.5 R205.1 S200.1 U200.4 | length 3150.9
  Top Layer w15: J200.5@-45,3011.85 -43.15,3010 145,3010 170,2985 v2(170,2135) ; v1(470,3010) S200.1@519.76,3010 523.11,3010 560,3046.89 R205.1@560,3119.69 C208.2@640,3119.69 ; v2(1414.25,2130.75) U200.4@1414.25,2185.63
  Bottom Layer w15: J200.5@-45,3011.85 -43.15,3010 v1(470,3010) ; v2(170,2135) 174.25,2130.75 v2(1414.25,2130.75)
M-SWCLK: J200.4 U200.19 | length 2118.3
  Top Layer w15: v2(1475,3110) 1477.24,3107.76 U200.19@1477.24,2514.37
  Bottom Layer w15: J200.4@-45,3111.85 -42.03,3108.88 1473.88,3108.88 v2(1475,3110)
M-SWDIO: J200.3 U200.18 | length 2253.5
  Top Layer w15: v2(1505,3215) 1508.74,3211.26 U200.18@1508.74,2514.37
  Bottom Layer w15: J200.3@-45,3211.85 -41.85,3215 v2(1505,3215)
MOTOR-A: C207.1 J101.5 Q300.3 Q303.2 R305.1 U200.24 | length 8212.4
  Top Layer w15: C207.1@924.84,2535 924.84,2589.84 v2(925,2590) ; U200.24@1319.76,2514.37 1319.76,2939.76 v2(1320,2940) ; v2(2134.75,2940.25) 2134.75,4696.8 2135,4697.05 2135,4845 2155,4865 3451.21,4865 3460,4856.21 R305.1@3460,4795.04 3763.22,4795.04 3772.01,4786.25 3772.01,4422.99 3775,4420
  Top Layer w100: Q303.2@3635,3962 3977,3962 3980,3965 ; 3980,4361.42 3980,3965 ; J101.5@4907.48,2962.09 4667.91,2962.09 4550,3080 4550,3616.42 4491.42,3675 4038.58,3675 3980,3733.58 3980,3965
  Bottom Layer w15: v2(925,2590) v2(1320,2590) ; v2@1319.76,2939.76 2134.26,2939.76 v2(2134.75,2940.25)
  other v1: 4500,2850 4600,2850 4700,2850 4800,2850 4900,2850 5000,2850 5100,2850 4500,2950 4600,2950 4700,2950 4800,2950 5000,2950 5100,2950 4200,3050 4300,3050 4400,3050 4500,3050 4600,3050 4700,3050 4800,3050 4900,3050 5000,3050 5100,3050 4200,3150 4300,3150 4400,3150 4500,3150 4600,3150 4200,3250 4300,3250 4400,3250 4500,3250 4600,3250 4600,3400 4600,3500 4200,3600 4300,3600 4400,3600 4500,3600 4600,3600 3800,3700 3900,3700 4000,3700 4100,3700 4200,3700 4300,3700 4400,3700 4500,3700 4600,3700 4700,3700 3800,3800 3900,3800 4000,3800 4100,3800 4200,3800 4300,3800 4400,3800 4500,3800 4600,3800 4700,3800 3800,3900 3900,3900 4000,3900 4100,3900 4500,3900 4600,3900 4700,3900 3800,4000 3900,4000 4000,4000 4100,4000 4500,4000 4600,4000 4700,4000 3800,4100 3900,4100 4000,4100 4100,4100 4200,4100 4300,4100 4400,4100 4500,4100 4600,4100 4700,4100 3800,4200 3900,4200 4000,4200 4100,4200 4200,4200 4300,4200 4400,4200 4500,4200 4600,4200 4700,4200 3800,4300 3900,4300 4000,4300 4100,4300 4200,4300 4300,4300 4400,4300 4500,4300 4600,4300 4700,4300 3800,4400 3900,4400 4000,4400 4100,4400
MOTOR-B: C206.1 J101.4 Q301.3 Q304.2 R303.1 U200.27 | length 6582.7
  Top Layer w15: C206.1@924.84,2350 925,2350.16 v2(925,2395) ; v2(1155,2395) v2@1155,2397.24 ; v2(1155,2775) v2@1155,2397.24 ; U200.27@1265.63,2397.24 v2@1155,2397.24 ; v2(2295,2775) 2295,3390 2315,3410 3146.21,3410 3155,3418.79 3155,3691.21 3163.79,3700 3451.21,3700 3460,3691.21 R303.1@3460,3650.04 3753.61,3650.04 3810,3593.65 3810,3300
  Top Layer w100: Q304.2@3635,2846 4036,2846 4040,2850 ; 4040,3245.42 4040,2850 ; J101.4@4907.48,2588.07 4098.58,2588.07 4040,2646.65 4040,2850
  Bottom Layer w15: v2(925,2395) v2(1155,2395) ; v2(1155,2775) v2(2295,2775)
  other v1: 3850,2500 3950,2500 4050,2500 4150,2500 4250,2500 4350,2500 4450,2500 4550,2500 4650,2500 4750,2500 4900,2500 5000,2500 5150,2500 3750,2600 3850,2600 3950,2600 4050,2600 4150,2600 4250,2600 4350,2600 4450,2600 4550,2600 4650,2600 4750,2600 5000,2600 5100,2600 3750,2700 3850,2700 3950,2700 4050,2700 4150,2700 4250,2700 4350,2700 4450,2700 4550,2700 4650,2700 4750,2700 4900,2700 5000,2700 5100,2700 3750,2800 3850,2800 3950,2800 4050,2800 3750,2900 3850,2900 3950,2900 4050,2900 3750,3000 3850,3000 3950,3000 4050,3000 3750,3100 3850,3100 3950,3100 4050,3100 3750,3200 3850,3200 3950,3200 4050,3200 3750,3300 3850,3300 3950,3300 4050,3300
